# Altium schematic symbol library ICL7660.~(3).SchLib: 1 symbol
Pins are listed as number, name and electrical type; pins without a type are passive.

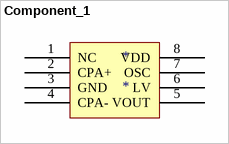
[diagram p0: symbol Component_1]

## Component_1
designator *
pins: 1 NC, 2 CPA+, 3 GND, 4 CPA-, 5 VOUT, 6 LV, 7 OSC, 8 VDD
